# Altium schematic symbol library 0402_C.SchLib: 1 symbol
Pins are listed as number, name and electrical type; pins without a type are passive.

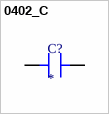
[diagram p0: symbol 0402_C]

## 0402_C
designator C?
MF: {'manufacturer': u'Panasonic Electronic Components'}; MP: ERJPA2F5601X
footprint 0402
pins: 1, 2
